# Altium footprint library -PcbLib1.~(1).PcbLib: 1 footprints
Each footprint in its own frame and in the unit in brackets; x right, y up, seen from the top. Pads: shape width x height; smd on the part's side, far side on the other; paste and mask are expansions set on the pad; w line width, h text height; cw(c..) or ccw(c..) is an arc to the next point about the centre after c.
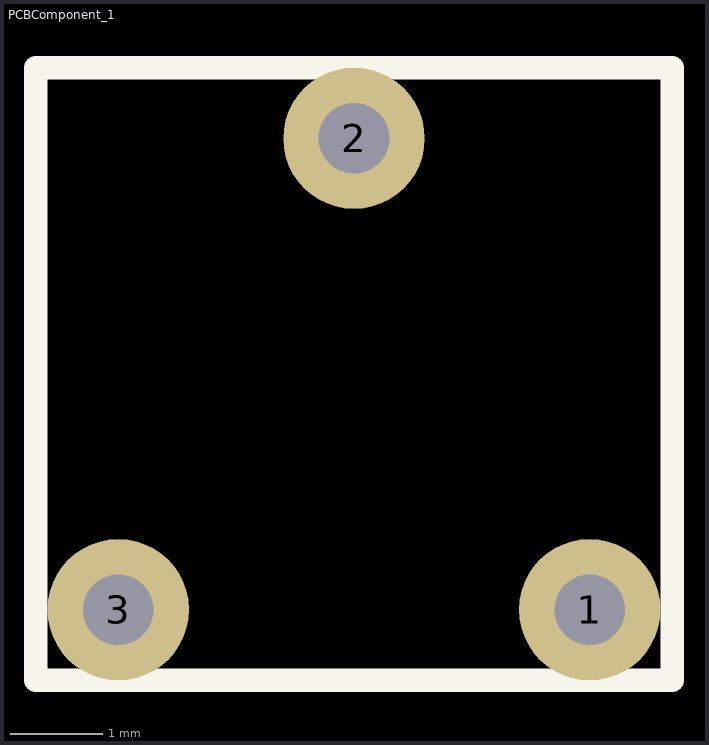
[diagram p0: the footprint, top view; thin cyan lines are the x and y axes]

## PCBComponent_1 [mil]
pads (3):
  round 60 hole 30: 1(-32200,-34000) 2(-32300,-33800) 3(-32400,-34000)
Top Overlay:
  lines w10: -32435,-34030 -32435,-33770 -32165,-33770 -32165,-34030 -32435,-34030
